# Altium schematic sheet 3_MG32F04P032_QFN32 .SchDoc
size 292 x 220 mm; PageSetup: Record=PageOptions|CenterHorizontal=True|CenterVertical=True|PrintScale=0.94|XCorrection=1.00|YCorrection=1.00|PrintKind=0|BorderSize=5000000|LeftOffset=0|BottomOffset=0|Orientation=2|PaperLength=1000|PaperWidth=1000|Scale=100|PaperSource=7|PrintQuality=-4|MediaType=1|DitherType=10|PaperKind=A4 (210 x 297 mm)|PrintScaleMode=1
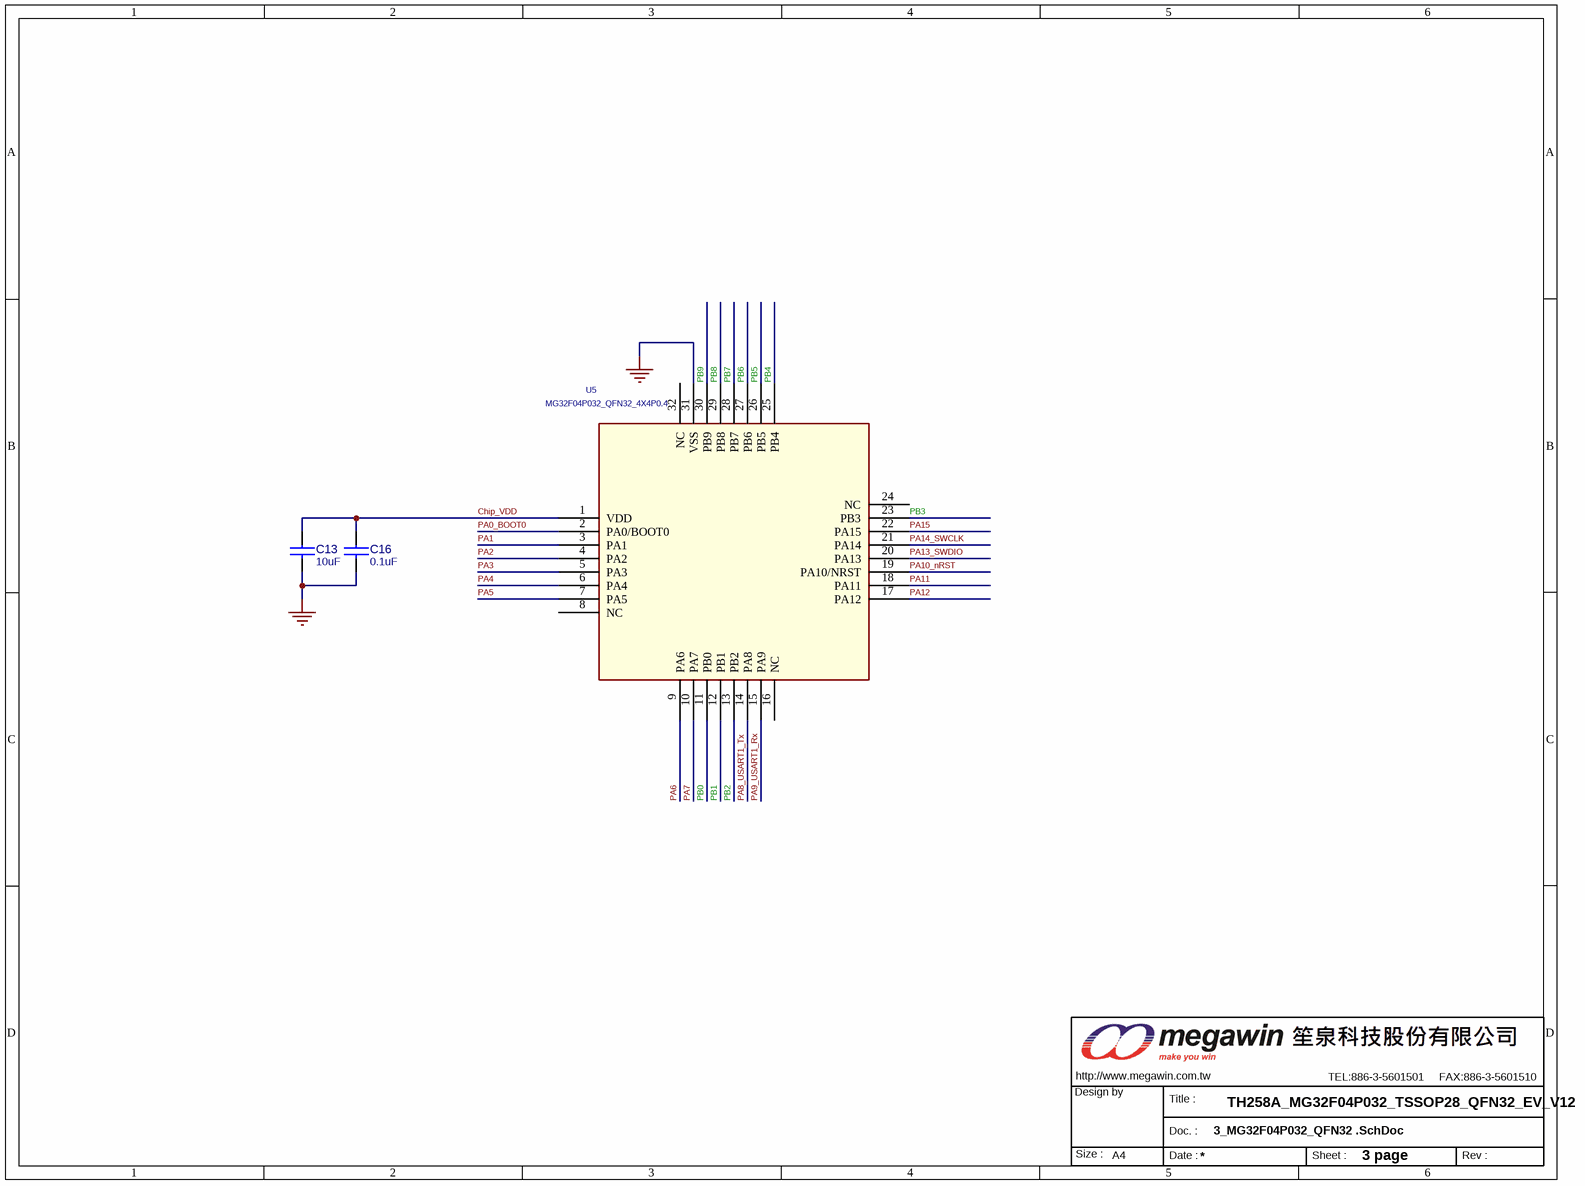
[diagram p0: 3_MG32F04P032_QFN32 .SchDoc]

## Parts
C13  10uF  [C-0603]
C16  0.1uF  [C-0603]
MW1  OrgAddr3: TEL:886-3-5601501     FAX:886-3-5601510  [MEGAWIN_3.4]  (hidden comment: MW-A4)  (graphical)
U5  MG32F04P032_QFN32_4X4P0.4  [QFN32_4X4P040]

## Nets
GND_POWER: C13.2 C16.2 U5.31(VSS)
Chip_VDD: C13.1 C16.1 U5.1(VDD)
PA0_BOOT0: U5.2(PA0/BOOT0)
PA1: U5.3(PA1)
PA2: U5.4(PA2)
PA3: U5.5(PA3)
PA4: U5.6(PA4)
PA5: U5.7(PA5)
PA6: U5.9(PA6)
PA7: U5.10(PA7)
PA8_USART1_Tx: U5.14(PA8)
PA9_USART1_Rx: U5.15(PA9)
PA10_nRST: U5.19(PA10/NRST)
PA11: U5.18(PA11)
PA12: U5.17(PA12)
PA13_SWDIO: U5.20(PA13)
PA14_SWCLK: U5.21(PA14)
PA15: U5.22(PA15)
PB0: U5.11(PB0)
PB1: U5.12(PB1)
PB2: U5.13(PB2)
PB3: U5.23(PB3)
PB4: U5.25(PB4)
PB5: U5.26(PB5)
PB6: U5.27(PB6)
PB7: U5.28(PB7)
PB8: U5.29(PB8)
PB9: U5.30(PB9)

Not connected (* = marked no-connect by the designer): U5 8(NC) 16(NC) 24(NC) 32(NC)

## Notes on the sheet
- TH258A_MG32F04P032_TSSOP28_QFN32_EV_V12
- 3 page

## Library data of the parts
C13 C16 = CAP NP_Dup1
MW1 = MW_A4_2
U5 = MG32F005_QFN32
